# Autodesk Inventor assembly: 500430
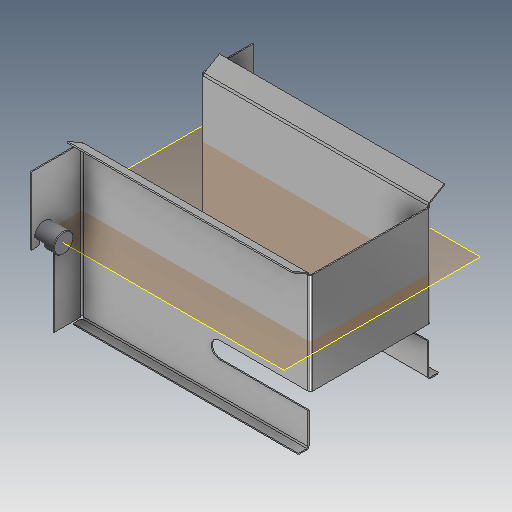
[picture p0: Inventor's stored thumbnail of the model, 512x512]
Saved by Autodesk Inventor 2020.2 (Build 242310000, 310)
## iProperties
Created: 2000-01
Part Number: 500430
Description: WMT-CP,SS,XX,SLEEVE,BUCKET,17_OZ
Document SubType Name: Assembly
Designer: glanglot
Mass: 395.424 g
Surface Area: 3605.61 cm^2
Volume: 279.36 cm^3
Density: 1.41546 g/cm^3
Control State: 0
Checked Out: False
Master: False
Shininess: 0.0
Length Units: 11269
Angle Units: 11279
Time Units: 11290
Mass Units: 11283
Length Display Precision: 3
Angle Display Precision: 2
Compacted: True
Dimensions: 301,6x212,6x292 mm
Mass: 0,395 kg
Density: 0.0
Volumn: 0.0
Area: 0.0
PropertySet Name: Model Information
Author: glanglot
Revision Number: -
Title: WMT-CP,SS,XX,SLEEVE,BUCKET,17_OZ
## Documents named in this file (3)
- D:\07 - DEMODATEN\OTX 2019 - Dataset - UPDATE - Dez2019\Designs\07-Packing machine\500430.iam
- D:\07 - DEMODATEN\OTX 2019 - Dataset - UPDATE - Dez2019\Designs\07-Packing machine\Parts\ADSK-011394.ipt
- D:\07 - DEMODATEN\OTX 2019 - Dataset - UPDATE - Dez2019\Designs\07-Packing machine\Parts\ADSK-011395.ipt
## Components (3 placed, 2 different names)
1. ADSK-011394:1 — Passend:1, Passend:3, Passend:5, Passend:6
2. ADSK-011395:1 — Passend:1, Passend:10, Fluchtend:1
3. ADSK-011395:2 — Passend:3, Passend:9, Fluchtend:1
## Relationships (7: Mate 6, Flush 1)
- Passend:1 [Mate]: ADSK-011394:1 ↔ ADSK-011395:1
- Passend:3 [Mate]: ADSK-011394:1 ↔ ADSK-011395:2
- Passend:5 [Mate]: ADSK-011394:1
- Passend:6 [Mate]: ADSK-011394:1
- Passend:9 [Mate]: ADSK-011395:2
- Passend:10 [Mate]: ADSK-011395:1
- Fluchtend:1 [Flush]: ADSK-011395:1 ↔ ADSK-011395:2
